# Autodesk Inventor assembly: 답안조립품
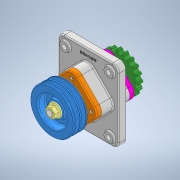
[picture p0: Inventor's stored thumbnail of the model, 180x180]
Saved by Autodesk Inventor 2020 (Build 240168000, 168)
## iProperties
Created: 2021-07
Part Number: 답안조립품
Document SubType Name: Assembly
Designer: Owner
Author: Owner
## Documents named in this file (16)
- C:\Users\Owner\Desktop\710707V1009\710707V1009\답안조립품.iam
- C:\Users\Owner\Desktop\710707V1009\710707V1009\본체.ipt
- C:\Users\Owner\Desktop\710707V1009\710707V1009\M16 너트.ipt
- C:\Users\Owner\Desktop\710707V1009\710707V1009\V-벨트풀리.ipt
- C:\Users\Owner\Desktop\710707V1009\710707V1009\멈춤나사 M4.ipt
- C:\Users\Owner\Desktop\710707V1009\710707V1009\베어링 6206.ipt
- C:\Users\Owner\Desktop\710707V1009\710707V1009\볼트 M6.ipt
- C:\Users\Owner\Desktop\710707V1009\710707V1009\부시.ipt
- C:\Users\Owner\Desktop\710707V1009\710707V1009\오일실 30x42x8.ipt
- C:\Users\Owner\Desktop\710707V1009\710707V1009\오일실 30x45x8.ipt
- C:\Users\Owner\Desktop\710707V1009\710707V1009\체인 스프로킷.ipt
- C:\Users\Owner\Desktop\710707V1009\710707V1009\축.ipt
- C:\Users\Owner\Desktop\710707V1009\710707V1009\커버A.ipt
- C:\Users\Owner\Desktop\710707V1009\710707V1009\커버B.ipt
- C:\Users\Owner\Desktop\710707V1009\710707V1009\키 6x6x18.ipt
- C:\Users\Owner\Desktop\710707V1009\710707V1009\키 6x6x20.ipt
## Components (3 placed, 2 different names)
1. M16 너트:1
2. V-벨트풀리:1 — 각도:1
3. M16 너트:2
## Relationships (1: Angle 1)
- 각도:1 [Angle]: V-벨트풀리:1
